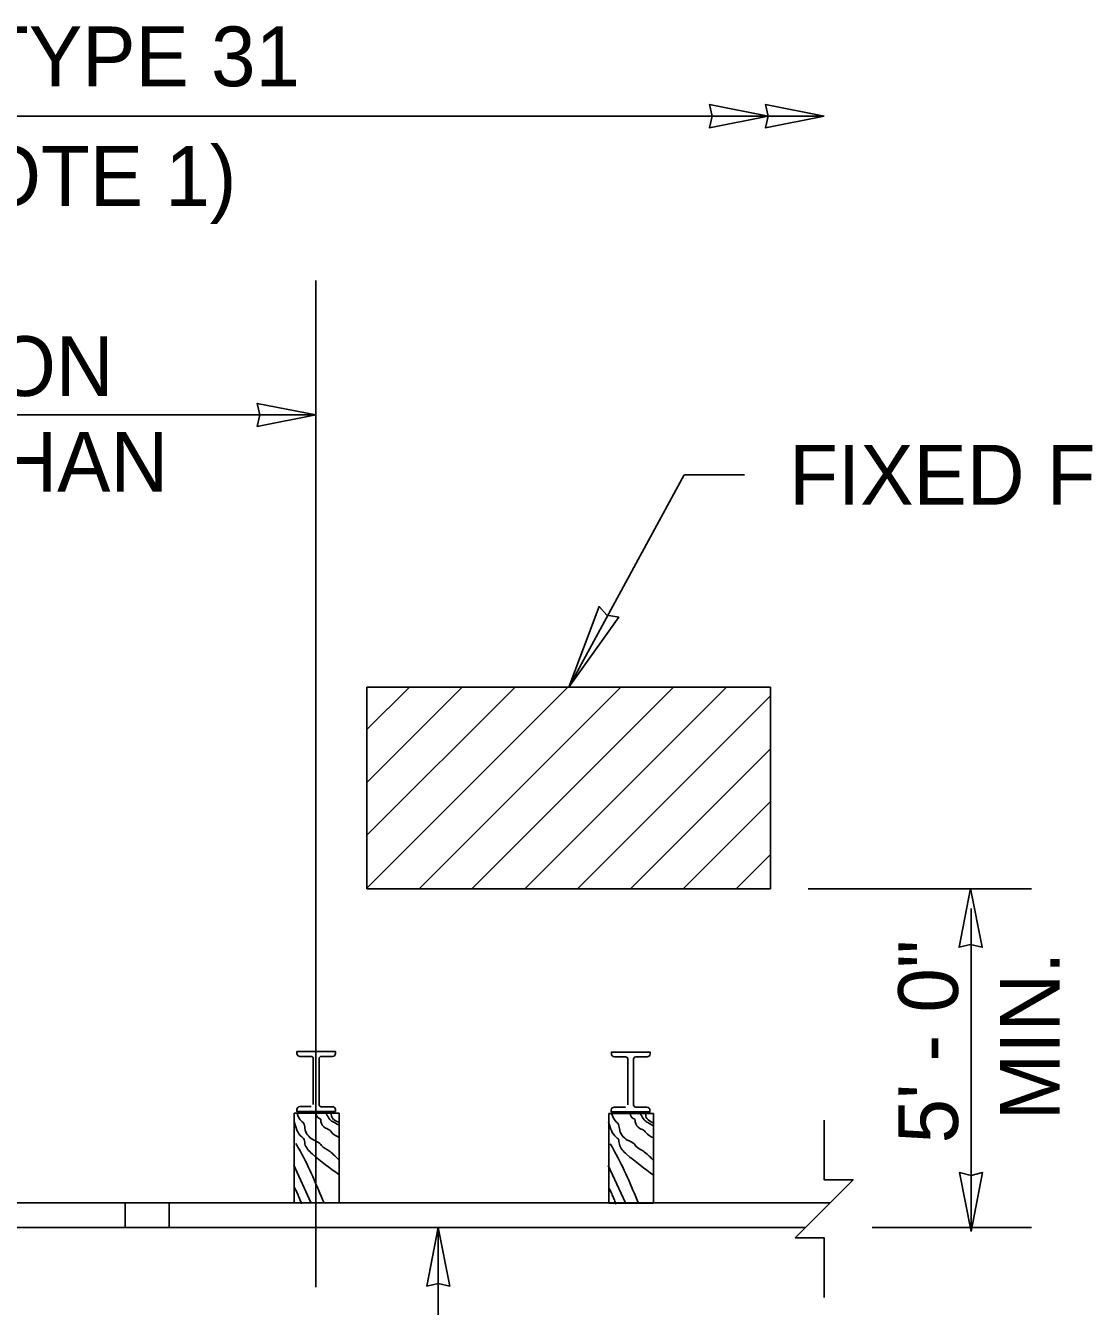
# Model space of a CAD drawing. Extents: x 99862 to 103680, y 99470 to 102076.
# Drawn here: x 101277.6 to 101562.6, y 100314.7 to 100657.5 of the extents above; entities that cross this region are included whole.
import ezdxf

# ---------------------------------------------------------------- set-up
doc = ezdxf.new("R2010")
doc.units = 0
for name, color, linetype in [('Level 1', 7, 'Continuous'), ('Level 10', 7, 'Continuous'), ('Level 11', 7, 'Continuous'), ('Level 13', 7, 'Continuous'), ('Level 15', 7, 'Continuous'), ('Level 17', 7, 'Continuous'), ('Level 20', 7, 'Continuous'), ('Level 4', 7, 'Continuous'), ('Level 9', 7, 'Continuous')]:
    doc.layers.add(name, color=color, linetype=linetype)

msp = doc.modelspace()

# ---------------------------------------------------------------- linework, layer by layer
at = {"layer": 'Level 1'}
for p, q in [((101492.93, 100342.5), (100981.02, 100342.5)), ((101486.32, 100335.89), (100974.41, 100335.89))]:
    msp.add_line(p, q, dxfattribs=at)
at = {"layer": 'Level 10'}
for p, q in [((101349.48, 100366.49), (101361.48, 100366.49)), ((101349.48, 100366.49), (101349.48, 100342.49)), ((101361.48, 100342.49), (101361.48, 100366.49)), ((101433.66, 100366.37), (101445.66, 100366.37)), ((101433.66, 100366.37), (101433.66, 100342.37)), ((101445.66, 100342.37), (101445.66, 100366.37)), ((101349.48, 100342.49), (101361.48, 100342.49)), ((101354.54, 100342.41), (101354.54, 100342.49)), ((101354.54, 100342.41), (101354.54, 100342.49)), ((101356.42, 100342.49), (101356.42, 100342.41)), ((101356.42, 100342.49), (101356.42, 100342.41)), ((101433.66, 100342.37), (101445.66, 100342.37)), ((101438.72, 100342.29), (101438.72, 100342.37)), ((101438.72, 100342.29), (101438.72, 100342.37)), ((101440.59, 100342.37), (101440.59, 100342.29)), ((101440.59, 100342.37), (101440.59, 100342.29))]:
    msp.add_line(p, q, dxfattribs=at)
at = {"layer": 'Level 11'}
for p, q in [((101304.19, 100342.5), (101304.19, 100335.89)), ((101315.97, 100342.5), (101315.97, 100335.89))]:
    msp.add_line(p, q, dxfattribs=at)
at = {"layer": 'Level 13'}
for p, q in [((101349.35, 100352.58), (101353.95, 100342.57)), ((101433.53, 100352.46), (101438.13, 100342.45))]:
    msp.add_line(p, q, dxfattribs=at)
for points in [[(101350.24, 100366.48), (101351.51, 100364.21), (101351.96, 100363.8), (101352.32, 100362.41), (101354.44, 100359.39), (101356.35, 100358.3), (101356.76, 100357.76), (101358.89, 100356.3), (101359.07, 100356.16), (101361.49, 100353.88)], [(101355.21, 100366.48), (101356.02, 100365.13), (101356.42, 100364.96), (101356.59, 100364.25), (101357.83, 100362.48), (101359.07, 100361.82), (101359.4, 100361.38), (101361.46, 100359.98)], [(101357.9, 100366.5), (101358.32, 100365.81), (101359.22, 100364.52), (101360.21, 100363.93), (101361.38, 100363.19)], [(101359.31, 100366.47), (101359.67, 100365.15), (101361.38, 100364.02)], [(101434.41, 100366.36), (101435.69, 100364.09), (101436.14, 100363.68), (101436.49, 100362.29), (101438.62, 100359.27), (101440.53, 100358.18), (101440.94, 100357.64), (101443.07, 100356.18), (101443.25, 100356.05), (101445.67, 100353.76)], [(101439.38, 100366.36), (101440.2, 100365.01), (101440.6, 100364.84), (101440.77, 100364.13), (101442.01, 100362.36), (101443.25, 100361.7), (101443.57, 100361.27), (101445.63, 100359.86)], [(101442.08, 100366.38), (101442.49, 100365.69), (101443.4, 100364.4), (101444.39, 100363.81), (101445.56, 100363.07)], [(101443.49, 100366.35), (101443.85, 100365.03), (101445.56, 100363.9)], [(101349.42, 100364.23), (101351.52, 100360.08), (101351.97, 100359.67), (101352.32, 100358.29), (101354.27, 100355.57), (101361.48, 100349.98)], [(101433.6, 100364.11), (101435.7, 100359.96), (101436.15, 100359.56), (101436.5, 100358.17), (101438.45, 100355.45), (101445.66, 100349.86)], [(101349.88, 100358.36), (101351.03, 100356.35), (101357.44, 100342.43)], [(101434.06, 100358.25), (101435.21, 100356.24), (101441.62, 100342.31)], [(101349.46, 100346.65), (101349.61, 100346.4), (101349.76, 100346.13), (101350.03, 100345.59), (101350.52, 100344.48), (101350.97, 100343.35), (101351.2, 100342.79), (101351.45, 100342.23)], [(101433.64, 100346.54), (101433.79, 100346.28), (101433.93, 100346.01), (101434.21, 100345.47), (101434.69, 100344.36), (101435.15, 100343.23), (101435.38, 100342.67), (101435.62, 100342.11)]]:
    msp.add_spline(points, degree=3, dxfattribs=at)
at = {"layer": 'Level 15'}
for p, q in [((101355.28, 100319.89), (101355.28, 100589.34)), ((101422.93, 100480.5), (101453.81, 100537.31)), ((101469.95, 100537.31), (101453.95, 100537.31)), ((101530.63, 100334.98), (101530.63, 100421.27)), ((101388.01, 100281.89), (101388.01, 100335.89))]:
    msp.add_line(p, q, dxfattribs=at)
for points in [[(101422.93, 100480.5), (101431.05, 100502.04), (101433.18, 100499.7), (101436.31, 100499.23)], [(101530.63, 100334.82), (101527.54, 100350.54), (101530.63, 100349.81), (101533.71, 100350.54)], [(101388.01, 100335.89), (101391.09, 100320.16), (101388.01, 100320.89), (101384.93, 100320.16)]]:
    msp.add_lwpolyline(points, close=True, dxfattribs=at)
msp.add_lwpolyline([(101491.3, 100364.62), (101491.3, 100348.62), (101499.04, 100348.62), (101483.56, 100333.13), (101491.3, 100333.13), (101491.3, 100317.13)], dxfattribs=at)
at = {"layer": 'Level 17'}
for p, q in [((101368.93, 100426.5), (101368.93, 100480.5)), ((101476.93, 100480.5), (101368.93, 100480.5)), ((101368.93, 100469.12), (101380.3, 100480.5)), ((101368.93, 100454.98), (101394.44, 100480.5)), ((101368.93, 100440.84), (101408.58, 100480.5)), ((101368.93, 100426.7), (101422.73, 100480.5)), ((101382.87, 100426.5), (101436.87, 100480.5)), ((101397.01, 100426.5), (101451.01, 100480.5)), ((101411.15, 100426.5), (101465.15, 100480.5)), ((101476.93, 100426.5), (101476.93, 100480.5)), ((101425.29, 100426.5), (101476.93, 100478.13)), ((101439.44, 100426.5), (101476.93, 100463.99)), ((101453.58, 100426.5), (101476.93, 100449.85)), ((101467.72, 100426.5), (101476.93, 100435.7)), ((101476.93, 100426.5), (101368.93, 100426.5))]:
    msp.add_line(p, q, dxfattribs=at)
at = {"layer": 'Level 20'}
for p, q in [((100933.41, 100633.28), (101491.3, 100633.28)), ((100933.41, 100553.33), (101355.28, 100553.33)), ((101487.02, 100426.5), (101546.82, 100426.5)), ((101504.19, 100335.89), (101546.82, 100335.89))]:
    msp.add_line(p, q, dxfattribs=at)
for points in [[(101476.3, 100633.28), (101460.58, 100630.2), (101461.31, 100633.28), (101460.58, 100636.36)], [(101491.3, 100633.28), (101475.58, 100630.2), (101476.3, 100633.28), (101475.58, 100636.36)], [(101355.28, 100553.33), (101339.56, 100550.25), (101340.28, 100553.33), (101339.56, 100556.41)], [(101530.52, 100426.61), (101527.44, 100410.88), (101530.52, 100411.61), (101533.61, 100410.88)]]:
    msp.add_lwpolyline(points, close=True, dxfattribs=at)
at = {"layer": 'Level 4'}
msp.add_line((101435.16, 100342.37), (101444.16, 100342.37), dxfattribs=at)
at = {"layer": 'Level 9'}
for p, q in [((101354.58, 100381.06), (101354.57, 100374.92)), ((101356.12, 100374.92), (101356.12, 100381.06)), ((101438.76, 100380.94), (101438.75, 100374.81)), ((101440.29, 100374.8), (101440.3, 100380.94)), ((101354.57, 100374.92), (101354.56, 100368.79)), ((101356.11, 100368.78), (101356.12, 100374.92)), ((101438.75, 100374.81), (101438.74, 100368.67)), ((101440.29, 100368.67), (101440.29, 100374.8))]:
    msp.add_line(p, q, dxfattribs=at)
for points in [[(101355.35, 100382.92), (101350.18, 100382.93), (101350.18, 100382.45)], [(101360.52, 100382.43), (101360.52, 100382.92), (101355.35, 100382.92)], [(101439.53, 100382.8), (101434.36, 100382.81), (101434.36, 100382.33)], [(101350.97, 100381.66), (101353.99, 100381.65)], [(101356.71, 100381.65), (101359.73, 100381.65)], [(101435.15, 100381.54), (101438.17, 100381.53)], [(101444.7, 100382.31), (101444.7, 100382.8), (101439.53, 100382.8)], [(101440.89, 100381.53), (101443.91, 100381.53)], [(101350.16, 100367.41), (101350.16, 100366.93), (101355.33, 100366.92)], [(101353.97, 100368.2), (101350.95, 100368.2)], [(101355.33, 100366.92), (101360.5, 100366.92), (101360.5, 100367.4)], [(101359.72, 100368.19), (101356.7, 100368.19)], [(101434.34, 100367.29), (101434.34, 100366.81), (101439.51, 100366.8)], [(101438.15, 100368.08), (101435.13, 100368.08)], [(101439.51, 100366.8), (101444.68, 100366.8), (101444.68, 100367.28)], [(101443.89, 100368.07), (101440.88, 100368.07)]]:
    msp.add_lwpolyline(points, dxfattribs=at)
for centre, radius, start, end in [((101350.97, 100382.44), 0.788, 179.9273, 269.9273), ((101353.99, 100381.06), 0.591, 359.9273, 89.9273), ((101356.71, 100381.06), 0.591, 89.9273, 179.9273), ((101359.74, 100382.43), 0.788, 269.9273, 359.9273), ((101435.15, 100382.33), 0.788, 179.9273, 269.9273), ((101438.17, 100380.94), 0.591, 359.9273, 89.9273), ((101440.89, 100380.94), 0.591, 89.9273, 179.9273), ((101443.91, 100382.31), 0.788, 269.9273, 359.9273), ((101350.95, 100367.41), 0.788, 89.9273, 179.9478), ((101356.7, 100368.78), 0.591, 179.9273, 269.9273), ((101359.72, 100367.4), 0.788, 359.9478, 89.9273), ((101435.13, 100367.29), 0.788, 89.9273, 179.9478), ((101440.88, 100368.66), 0.591, 179.9273, 269.9273), ((101443.89, 100367.28), 0.788, 359.9478, 89.9273)]:
    msp.add_arc(centre, radius, start, end, dxfattribs=at)

# ---------------------------------------------------------------- texts
at = {"layer": 'Level 15'}
for s, p in [('5\' - 0" ', (101527.14, 100358.37)), ('MIN.', (101554.34, 100364.53))]:
    msp.add_text(s, height=16, rotation=90, dxfattribs=at).set_placement(p)
at = {"layer": 'Level 20'}
for s, p in [('BEAM GUARDRAIL TYPE 31 ', (101068.02, 100641.28)), ('PAY LIMIT (SEE NOTE 1)', (101084.33, 100609.28)), ('BEAM GUARDRAIL EXTENSION', (100980.13, 100558.39)), ('LENGTH VARIES (GREATER THAN ', (100963.84, 100532.79))]:
    msp.add_text(s, height=16, dxfattribs=at).set_placement(p)
msp.add_text('FIXED FEATURE', height=16, rotation=360, dxfattribs=at).set_placement((101481.95, 100529.31))

doc.saveas('drawing.dxf')
